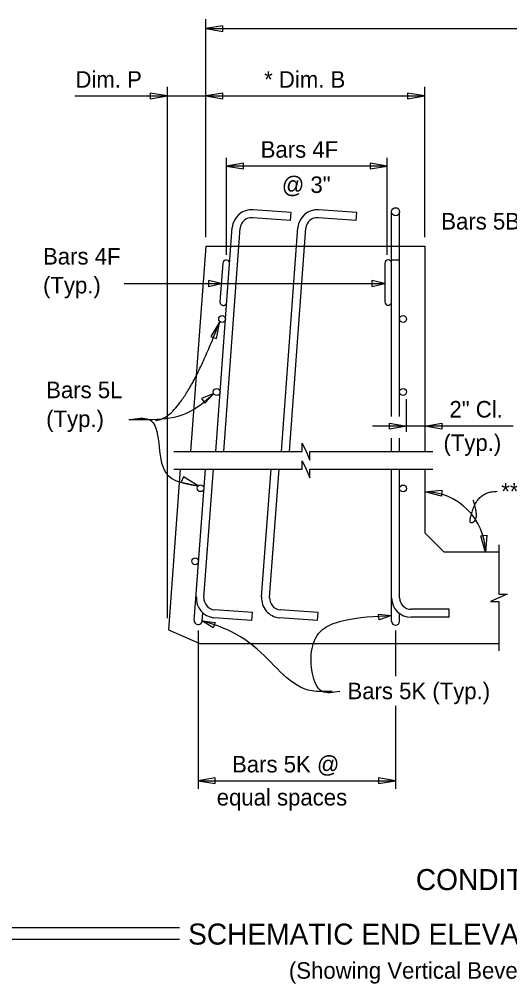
# Model space of a CAD drawing. Extents: x 120790.7 to 120844.8, y 120612.1 to 120653.6.
# Drawn here: x 120801.28 to 120805.76, y 120612.08 to 120620.9 of the extents above; entities that cross this region are included whole.
import ezdxf

# ---------------------------------------------------------------- set-up
doc = ezdxf.new("R2010")
doc.units = 0
for name, color, linetype in [('AdhocPoint_dp', 7, 'Continuous'), ('Patterning', 7, 'Continuous'), ('PlotBorder_dp', 7, 'Continuous'), ('SheetBorder_dp', 7, 'Continuous')]:
    doc.layers.add(name, color=color, linetype=linetype)

# ---------------------------------------------------------------- blocks, each defined once
blk = doc.blocks.new('Terminator-Arrow')
at = {"layer": 'PlotBorder_dp'}
blk.add_lwpolyline([(0, 0), (-0.00041, 0.000069), (-0.00041, -0.000069)], close=True, dxfattribs=at)

msp = doc.modelspace()

# ---------------------------------------------------------------- linework, layer by layer
at = {"layer": 'AdhocPoint_dp'}
for p, q in [((120802.9858, 120618.8231), (120802.8471, 120616.945)), ((120802.9858, 120618.8231), (120804.9858, 120618.8231)), ((120804.9858, 120618.8231), (120804.9858, 120616.945)), ((120802.7526, 120616.7833), (120802.6441, 120615.3142)), ((120804.9858, 120616.7833), (120804.9858, 120616.2012)), ((120805.1626, 120616.0244), (120804.9858, 120616.2012)), ((120805.6632, 120616.0244), (120805.1626, 120616.0244)), ((120802.6441, 120615.3142), (120802.9313, 120615.1911)), ((120802.9313, 120615.1911), (120805.6632, 120615.1911))]:
    msp.add_line(p, q, dxfattribs=at)
at = {"layer": 'PlotBorder_dp'}
for p, q in [((120802.9858, 120618.9058), (120802.9858, 120620.8956)), ((120802.9858, 120618.9058), (120802.9858, 120620.8956)), ((120802.635, 120615.4226), (120802.635, 120620.2796)), ((120802.635, 120615.4226), (120802.635, 120620.2796)), ((120804.9858, 120618.9058), (120804.9858, 120620.2796)), ((120804.9858, 120618.9058), (120804.9858, 120620.2796)), ((120801.7897, 120620.1951), (120804.9857, 120620.1951)), ((120801.7897, 120620.1951), (120804.9857, 120620.1951)), ((120803.1748, 120618.7443), (120803.1748, 120619.6306)), ((120803.1748, 120618.7443), (120803.1748, 120619.6306)), ((120803.1748, 120619.555), (120804.6436, 120619.555)), ((120803.1748, 120619.555), (120804.6436, 120619.555)), ((120804.6436, 120618.7443), (120804.6436, 120619.6306)), ((120804.6436, 120618.7443), (120804.6436, 120619.6306)), ((120802.2416, 120618.4811), (120804.6212, 120618.4811)), ((120802.2416, 120618.4811), (120804.6212, 120618.4811)), ((120804.8192, 120617.124), (120804.8192, 120617.4243)), ((120804.8192, 120617.124), (120804.8192, 120617.4243)), ((120805.7938, 120617.1779), (120804.5091, 120617.1779)), ((120805.7938, 120617.1779), (120804.5091, 120617.1779)), ((120802.9169, 120615.3084), (120802.9169, 120613.8613)), ((120802.9169, 120615.3084), (120802.9169, 120613.8613)), ((120804.7202, 120615.3084), (120804.7202, 120614.8935)), ((120804.7202, 120615.3084), (120804.7202, 120614.8935)), ((120804.7202, 120614.6214), (120804.7202, 120613.8613)), ((120804.7202, 120614.6214), (120804.7202, 120613.8613)), ((120802.9169, 120613.9369), (120804.7202, 120613.9369)), ((120802.9169, 120613.9369), (120804.7202, 120613.9369)), ((120802.747, 120612.5928), (120795.4968, 120612.5928)), ((120802.747, 120612.5928), (120795.4968, 120612.5928)), ((120802.747, 120612.4847), (120795.4968, 120612.4847)), ((120802.747, 120612.4847), (120795.4968, 120612.4847))]:
    msp.add_line(p, q, dxfattribs=at)
for points in [[(120802.9857, 120620.8104), (120806.2671, 120620.8104), (120806.2671, 120620.8621), (120806.2896, 120620.8104), (120806.3121, 120620.7588), (120806.3121, 120620.8104), (120809.5936, 120620.8104)], [(120802.9857, 120620.8104), (120806.2671, 120620.8104), (120806.2671, 120620.8621), (120806.2896, 120620.8104), (120806.3121, 120620.7588), (120806.3121, 120620.8104), (120809.5936, 120620.8104)], [(120802.6927, 120616.9451), (120803.8679, 120616.9451), (120803.8679, 120617.0226), (120803.9017, 120616.9451), (120803.9354, 120616.8676), (120803.9354, 120616.9451), (120805.0615, 120616.9451)], [(120802.6927, 120616.9451), (120803.8679, 120616.9451), (120803.8679, 120617.0226), (120803.9017, 120616.9451), (120803.9354, 120616.8676), (120803.9354, 120616.9451), (120805.0615, 120616.9451)], [(120802.6927, 120616.7834), (120803.8679, 120616.7834), (120803.8679, 120616.8609), (120803.9017, 120616.7834), (120803.9354, 120616.7059), (120803.9354, 120616.7834), (120805.0615, 120616.7834)], [(120802.6927, 120616.7834), (120803.8679, 120616.7834), (120803.8679, 120616.8609), (120803.9017, 120616.7834), (120803.9354, 120616.7059), (120803.9354, 120616.7834), (120805.0615, 120616.7834)], [(120805.6632, 120616.0915), (120805.6632, 120615.6415), (120805.7407, 120615.6415), (120805.5857, 120615.574), (120805.6632, 120615.574), (120805.6632, 120615.124)], [(120805.6632, 120616.0915), (120805.6632, 120615.6415), (120805.7407, 120615.6415), (120805.5857, 120615.574), (120805.6632, 120615.574), (120805.6632, 120615.124)]]:
    msp.add_lwpolyline(points, dxfattribs=at)
for points in [[(120803.1277, 120618.4811), (120803.0105, 120618.5075), (120803.0105, 120618.4546)], [(120803.1277, 120618.4811), (120803.0105, 120618.5075), (120803.0105, 120618.4546)], [(120804.6213, 120618.4811), (120804.5041, 120618.5075), (120804.5041, 120618.4546)], [(120804.6213, 120618.4811), (120804.5041, 120618.5075), (120804.5041, 120618.4546)], [(120803.113, 120618.1343), (120803.033, 120617.9976), (120803.0825, 120617.9789)], [(120803.113, 120618.1343), (120803.033, 120617.9976), (120803.0825, 120617.9789)], [(120803.058, 120617.4756), (120802.9474, 120617.4288), (120802.9783, 120617.3858)], [(120803.058, 120617.4756), (120802.9474, 120617.4288), (120802.9783, 120617.3858)], [(120802.9163, 120616.6318), (120802.7813, 120616.7148), (120802.7615, 120616.6657)], [(120802.9163, 120616.6318), (120802.7813, 120616.7148), (120802.7615, 120616.6657)], [(120804.9858, 120616.5778), (120805.1437, 120616.5909), (120805.1392, 120616.5382)], [(120804.9858, 120616.5778), (120805.1437, 120616.5909), (120805.1392, 120616.5382)], [(120805.5406, 120616.0225), (120805.4995, 120616.1755), (120805.5521, 120616.1805)], [(120805.5406, 120616.0225), (120805.4995, 120616.1755), (120805.5521, 120616.1805)], [(120804.6831, 120615.4465), (120804.5695, 120615.4075), (120804.5638, 120615.4601)], [(120804.6831, 120615.4465), (120804.5695, 120615.4075), (120804.5638, 120615.4601)], [(120802.9532, 120615.3979), (120803.0724, 120615.3833), (120803.0546, 120615.3335)], [(120802.9532, 120615.3979), (120803.0724, 120615.3833), (120803.0546, 120615.3335)]]:
    msp.add_lwpolyline(points, close=True, dxfattribs=at)
msp.add_arc((120804.9815, 120616.0186), 0.5592, 0.39914, 89.54996, dxfattribs=at)
msp.add_arc((120804.9815, 120616.0186), 0.5592, 0.39914, 89.54996, dxfattribs=at)
for points in [[(120802.5275, 120617.2316), (120802.7713, 120617.2316), (120803.113, 120618.1343)], [(120802.5275, 120617.2316), (120802.7713, 120617.2316), (120803.113, 120618.1343)], [(120805.4263, 120616.5051), (120805.4836, 120616.3332), (120805.3728, 120616.2645), (120805.4855, 120616.5815), (120805.6485, 120616.5815)], [(120805.4263, 120616.5051), (120805.4836, 120616.3332), (120805.3728, 120616.2645), (120805.4855, 120616.5815), (120805.6485, 120616.5815)]]:
    msp.add_open_spline(points, degree=2, dxfattribs=at)
for points in [[(120802.2837, 120617.2385), (120802.5034, 120617.2385), (120802.804, 120617.2935), (120803.058, 120617.4756)], [(120802.2837, 120617.2385), (120802.5034, 120617.2385), (120802.804, 120617.2935), (120803.058, 120617.4756)], [(120802.2924, 120617.2385), (120802.4658, 120617.2385), (120802.6205, 120616.751), (120802.9163, 120616.6318)], [(120802.2924, 120617.2385), (120802.4658, 120617.2385), (120802.6205, 120616.751), (120802.9163, 120616.6318)], [(120804.2098, 120614.7531), (120804.0482, 120614.7531), (120803.9606, 120614.9176), (120804.051, 120615.3177), (120804.2317, 120615.3972), (120804.6832, 120615.4465)], [(120804.2098, 120614.7531), (120804.0482, 120614.7531), (120803.9606, 120614.9176), (120804.051, 120615.3177), (120804.2317, 120615.3972), (120804.6832, 120615.4465)], [(120804.1414, 120614.7531), (120804.0346, 120614.7531), (120803.9935, 120614.7531), (120803.4923, 120615.1067), (120803.1773, 120615.3177), (120802.9533, 120615.398)], [(120804.1414, 120614.7531), (120804.0346, 120614.7531), (120803.9935, 120614.7531), (120803.4923, 120615.1067), (120803.1773, 120615.3177), (120802.9533, 120615.398)]]:
    msp.add_spline(points, degree=3, dxfattribs=at)
at = {"layer": 'SheetBorder_dp'}
for p, q in [((120803.7646, 120619.1291), (120803.4177, 120619.1548)), ((120803.7592, 120619.0564), (120803.7646, 120619.1291)), ((120804.3646, 120619.1291), (120804.0177, 120619.1548)), ((120804.3592, 120619.0564), (120804.3646, 120619.1291)), ((120804.6837, 120617.266), (120804.6837, 120619.1363)), ((120804.7567, 120617.266), (120804.7567, 120619.1363)), ((120803.7592, 120619.0564), (120803.4123, 120619.082)), ((120804.3592, 120619.0564), (120804.0123, 120619.082)), ((120803.0769, 120616.945), (120803.228, 120618.9912)), ((120803.15, 120616.945), (120803.3007, 120618.9858)), ((120803.6769, 120616.945), (120803.828, 120618.9912)), ((120803.75, 120616.945), (120803.9007, 120618.9858)), ((120804.6837, 120618.6981), (120804.7567, 120618.6981)), ((120803.1414, 120618.6668), (120803.1153, 120618.3136)), ((120804.6212, 120618.6668), (120804.6212, 120618.3127)), ((120804.6837, 120616.945), (120804.6837, 120617.0681)), ((120804.7567, 120616.945), (120804.7567, 120617.0681)), ((120802.8832, 120615.4397), (120802.9824, 120616.7833)), ((120802.969, 120615.6109), (120803.0555, 120616.7833)), ((120803.4962, 120615.6163), (120803.5824, 120616.7833)), ((120803.569, 120615.6109), (120803.6555, 120616.7833)), ((120804.6837, 120615.4306), (120804.6837, 120616.7833)), ((120804.7567, 120615.6078), (120804.7567, 120616.7833)), ((120803.4121, 120615.4737), (120803.0652, 120615.4993)), ((120804.0121, 120615.4737), (120803.6652, 120615.4993)), ((120805.2087, 120615.5036), (120804.8609, 120615.5036)), ((120805.2087, 120615.4306), (120805.2087, 120615.5036)), ((120802.8805, 120615.4033), (120802.8832, 120615.4397)), ((120802.9532, 120615.3979), (120802.9584, 120615.4681)), ((120803.4068, 120615.401), (120803.0598, 120615.4266)), ((120803.4068, 120615.401), (120803.4121, 120615.4737)), ((120804.0068, 120615.401), (120803.6598, 120615.4266)), ((120804.0068, 120615.401), (120804.0121, 120615.4737)), ((120804.6837, 120615.3942), (120804.6837, 120615.4306)), ((120804.7567, 120615.3942), (120804.7567, 120615.4645)), ((120805.2087, 120615.4306), (120804.8609, 120615.4306))]:
    msp.add_line(p, q, dxfattribs=at)
for centre, radius in [((120804.7202, 120619.1373), 0.0365), ((120803.1351, 120618.1564), 0.0312), ((120804.7879, 120618.1564), 0.0312), ((120803.0859, 120617.4898), 0.0312), ((120804.7879, 120617.4898), 0.0312), ((120802.9383, 120616.6097), 0.0312), ((120804.7879, 120616.6077), 0.0312), ((120802.889, 120615.9419), 0.0312)]:
    msp.add_circle(centre, radius, dxfattribs=at)
for centre, radius, start, end in [((120803.4046, 120618.9781), 0.1771, 85.77683, 175.77683), ((120804.0046, 120618.9781), 0.1771, 85.77683, 175.77683), ((120803.4046, 120618.9781), 0.1042, 85.77683, 175.77683), ((120804.0046, 120618.9781), 0.1042, 85.77683, 175.77683), ((120803.1725, 120618.6645), 0.0312, 355.77683, 175.77683), ((120804.6525, 120618.6668), 0.0312, 0, 180), ((120803.1465, 120618.3113), 0.0312, 175.77683, 355.77683), ((120804.6525, 120618.3127), 0.0312, 180, 0), ((120803.075, 120615.6012), 0.1752, 175.04658, 265.04658), ((120803.0729, 120615.6033), 0.1042, 175.77683, 265.77683), ((120803.6729, 120615.6033), 0.1771, 175.77683, 265.77683), ((120803.6729, 120615.6033), 0.1042, 175.77683, 265.77683), ((120804.8609, 120615.6078), 0.1771, 180, 270), ((120804.8609, 120615.6078), 0.1042, 180, 270), ((120802.9169, 120615.4006), 0.0365, 175.77683, 355.77683), ((120804.7202, 120615.3942), 0.0365, 180, 0)]:
    msp.add_arc(centre, radius, start, end, dxfattribs=at)

# ---------------------------------------------------------------- block references
at = {"layer": 'PlotBorder_dp', "xscale": 381, "rotation": 180}
for p, yscale in [((120802.9856, 120620.8099), 384.0238095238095), ((120802.9856, 120620.8099), 384.0238095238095), ((120802.9856, 120620.1947), 384.0238095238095), ((120802.9856, 120620.1947), 384.0238095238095), ((120803.1747, 120619.5547), 384.0238095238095), ((120803.1747, 120619.5547), 384.0238095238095), ((120804.9857, 120617.1775), -384.0238095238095), ((120804.9857, 120617.1775), -384.0238095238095), ((120802.9166, 120613.9365), 384.0238095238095), ((120802.9166, 120613.9365), 384.0238095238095)]:
    msp.add_blockref('Terminator-Arrow', p, dxfattribs=dict(at, yscale=yscale))
at = {"layer": 'PlotBorder_dp', "xscale": 381}
for p, yscale in [((120802.6348, 120620.1947), 384.0238095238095), ((120802.6348, 120620.1947), 384.0238095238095), ((120804.9856, 120620.1947), 384.0238095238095), ((120804.9856, 120620.1947), 384.0238095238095), ((120804.6434, 120619.5547), 384.0238095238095), ((120804.6434, 120619.5547), 384.0238095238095), ((120804.8191, 120617.1775), -384.0238095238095), ((120804.8191, 120617.1775), -384.0238095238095), ((120804.72, 120613.9365), 384.0238095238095), ((120804.72, 120613.9365), 384.0238095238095)]:
    msp.add_blockref('Terminator-Arrow', p, dxfattribs=dict(at, yscale=yscale))

# ---------------------------------------------------------------- texts
at = {"layer": 'Patterning'}
for s, height, p in [('Dim. P', 0.1512, (120801.7949, 120620.2702)), ('* Dim. B', 0.1512, (120803.5189, 120620.2702)), ('Bars 4F', 0.1512, (120803.4873, 120619.6303)), ('@ 3"', 0.1512, (120803.6805, 120619.3082)), ('Bars 5B (Typ.)', 0.1512, (120805.1374, 120618.9742)), ('2" Cl.', 0.1512, (120805.2121, 120617.256)), ('(Typ.)', 0.1512, (120805.1574, 120616.9507)), ('** 90°', 0.1512, (120805.6851, 120616.5056)), ('Bars 5K (Typ.)', 0.1512, (120804.2803, 120614.6816)), ('Bars 5K @', 0.1512, (120803.2258, 120614.0122)), ('equal spaces', 0.1512, (120803.0859, 120613.7099)), ('CONDITION 2', 0.192, (120804.9048, 120612.9373)), ('SCHEMATIC END ELEVATIONS OF BEAMS', 0.192, (120802.8243, 120612.439)), ('(Showing Vertical Bevel of Beam End)', 0.1512, (120803.7453, 120612.1271))]:
    msp.add_text(s, height=height, dxfattribs=at).set_placement(p)
at = {"layer": 'PlotBorder_dp'}
for s, p in [('Bars 4F', (120801.499, 120618.654)), ('(Typ.)', (120801.499, 120618.39)), ('Bars 5L', (120801.5277, 120617.4326)), ('(Typ.)', (120801.5277, 120617.1686))]:
    msp.add_text(s, height=0.1512, dxfattribs=at).set_placement(p)

doc.saveas('drawing.dxf')
